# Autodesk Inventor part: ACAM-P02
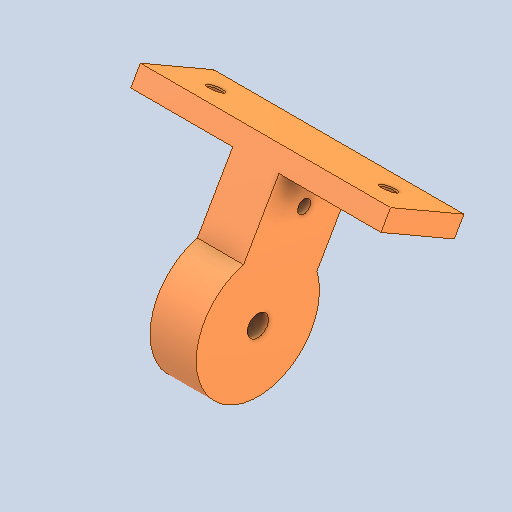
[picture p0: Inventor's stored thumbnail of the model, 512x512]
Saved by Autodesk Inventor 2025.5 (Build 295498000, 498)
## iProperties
Created: 2026-10
Part Number: ACAM-P02
Material: Genérico
Document SubType Name: Modeling
Designer: Luis M
Density: 1 g/cm^3
Appearance: Valor por defecto
Description: Placa portacámara
Material_BOM: PLA
Proceso_BOM: Impresión 3D
Author: Luis M
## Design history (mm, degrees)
feature "Base1"
node "Sólido1"
